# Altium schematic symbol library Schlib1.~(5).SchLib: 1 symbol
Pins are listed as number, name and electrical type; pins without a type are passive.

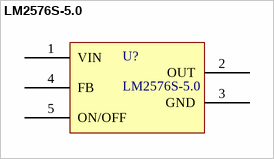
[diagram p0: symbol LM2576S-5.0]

## LM2576S-5.0
designator U?
footprint TO263-5A (263，5脚晶体管)
pins: 1 VIN, 2 OUT, 3 GND, 4 FB, 5 ON/OFF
